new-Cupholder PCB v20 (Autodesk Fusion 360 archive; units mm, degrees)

design "EIP Cupholder PCB"
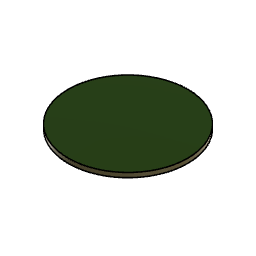
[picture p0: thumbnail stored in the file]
derived_context "DerivedContext1"
sketch "Outline" plane through (0, 0, 0) normal (0, 0, 1) x axis (1, 0, 0)
step sketch "pcb-sketch"
canvas "Canvas1" bodies "Board"
canvas "Canvas2" bodies "Board"
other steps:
pcbextrude "PCBExtrude"
pcbextrude "PCBExtrude1"
derived_base_feature "pcb-sketch"
derived_base_feature "Base Feature"
box_primitive "BoxPrimitive1" DistanceX 8 DistanceY 3.81 DistanceZ 0.1 OffsetDistanceX 0 OffsetDistanceY 0
base_feature "Base Feature"
box_primitive "BoxPrimitive1" DistanceX 20 DistanceY 17.95 DistanceZ 1 OffsetDistanceX 0 OffsetDistanceY 0
pcbextrude "PCBExtrude1"
pcbextrude "PCBExtrude1"
extrude "Extrude1" sketch "pcb-sketch" blind 1.5 bodies "Board"
pcbextrude "PCBExtrude1"
pcbextrude "PCBExtrude"
create_component "CreateComponent1"
create_component "CreateComponent2"
create_component "CreateComponent3"
create_component "CreateComponent4"
create_component "CreateComponent5"
create_component "CreateComponent6"
create_component "CreateComponent3"
as_built_joint "As-built1"
create_component "CreateComponent5"
create_component "CreateComponent6"
step "CreateComponent"
named bodies: "Board"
